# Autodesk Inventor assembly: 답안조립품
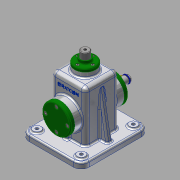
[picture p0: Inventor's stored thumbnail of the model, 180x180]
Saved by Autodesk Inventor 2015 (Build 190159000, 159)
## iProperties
Created: 2016-02
Part Number: 답안조립품
Document SubType Name: Assembly
Designer: Administrator
Author: Administrator
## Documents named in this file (19)
- C:\Users\Administrator\Desktop\460219V1007\답안조립품.iam
- C:\Users\Administrator\Desktop\460219V1007\본체.ipt
- C:\Users\Administrator\Desktop\460219V1007\V-벨트풀리.ipt
- C:\Users\Administrator\Desktop\460219V1007\고정핀.ipt
- C:\Users\Administrator\Desktop\460219V1007\뒤커버.ipt
- C:\Users\Administrator\Desktop\460219V1007\링크.ipt
- C:\Users\Administrator\Desktop\460219V1007\멈춤링 6 x 5.ipt
- C:\Users\Administrator\Desktop\460219V1007\멈춤링 15 x 1.ipt
- C:\Users\Administrator\Desktop\460219V1007\베어링 15 x 35 x 11.ipt
- C:\Users\Administrator\Desktop\460219V1007\볼트 M3 x 8.ipt
- C:\Users\Administrator\Desktop\460219V1007\볼트 M4 x 10.ipt
- C:\Users\Administrator\Desktop\460219V1007\볼트 M6 x 12.ipt
- C:\Users\Administrator\Desktop\460219V1007\상부부시.ipt
- C:\Users\Administrator\Desktop\460219V1007\슬라이드바.ipt
- C:\Users\Administrator\Desktop\460219V1007\앞커버.ipt
- C:\Users\Administrator\Desktop\460219V1007\오일실 15 25 7.ipt
- C:\Users\Administrator\Desktop\460219V1007\와셔.ipt
- C:\Users\Administrator\Desktop\460219V1007\키 5 x 5 x 14.ipt
- C:\Users\Administrator\Desktop\460219V1007\편심축.ipt
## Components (15 placed, 5 different names)
1. V-벨트풀리:1
2. 고정핀:1
3. ISO 4018 M6 x 12:1
4. ISO 4762 M3 x 8:1
5. ISO 4762 M3 x 8:2
6. ISO 4762 M3 x 8:3
7. ISO 4762 M3 x 8:4
8. ISO 4762 M4 x 10:1
9. ISO 4762 M4 x 10:3
10. ISO 4762 M4 x 10:4
11. ISO 4762 M4 x 10:5
12. ISO 4762 M4 x 10:2
13. ISO 4762 M4 x 10:6
14. ISO 4762 M4 x 10:7
15. ISO 4762 M4 x 10:8
